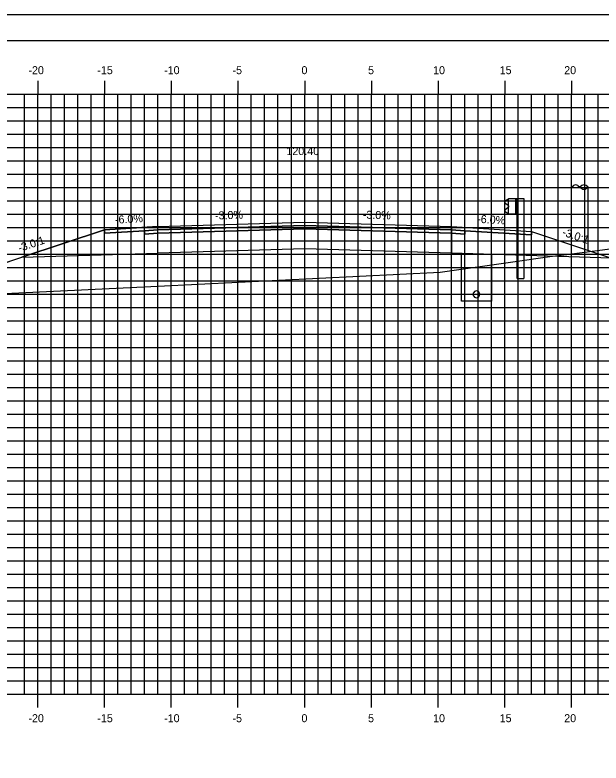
# Model space of a CAD drawing. Extents: x 850598 to 870284, y 366541 to 366651.
# Drawn here: x 852181.5 to 852225.4, y 366595.1 to 366651.2 of the extents above; entities that cross this region are included whole.
import ezdxf

# ---------------------------------------------------------------- set-up
doc = ezdxf.new("R2010")
doc.units = 0
for name, color, linetype in [('ANNOTATION', 7, 'Continuous'), ('BORDER', 7, 'Continuous'), ('D_Drainage_Underdrain', 7, 'Continuous'), ('D_Drainage_Underdrain_06in', 7, 'Continuous'), ('D_Guardrail_Beam_Rt', 7, 'Continuous'), ('D_Roadway_Centerline', 7, 'Continuous'), ('D_Roadway_Centerline_Text', 7, 'Continuous'), ('D_Roadway_Edge_Shoulder', 7, 'Continuous'), ('D_Roadway_Edge_TW', 7, 'Continuous'), ('D_Roadway_Pavement', 7, 'Continuous'), ('D_Roadway_SlopeLines', 7, 'Continuous'), ('D_Roadway_SubGrade', 7, 'Continuous'), ('D_Utilities_Pole_Joint', 7, 'Continuous'), ('H_V ANNOTATION', 7, 'Continuous'), ('MAJOR', 7, 'Continuous'), ('MINOR', 7, 'Continuous'), ('PLOT BOUNDARY', 7, 'Continuous'), ('S_Roadway_Centerline', 7, 'Continuous')]:
    doc.layers.add(name, color=color, linetype=linetype)

msp = doc.modelspace()

# ---------------------------------------------------------------- linework, layer by layer
at = {"layer": 'BORDER'}
msp.add_line((852318.193, 366649.225), (852158.193, 366649.225), dxfattribs=at)
at = {"layer": 'D_Drainage_Underdrain'}
msp.add_lwpolyline([(852217.193, 366633.214), (852217.193, 366629.714), (852214.943, 366629.714), (852214.943, 366633.259)], close=True, dxfattribs=at)
at = {"layer": 'D_Drainage_Underdrain_06in'}
msp.add_lwpolyline([(852216.068, 366630.464), (852215.99, 366630.451), (852215.921, 366630.416), (852215.865, 366630.361), (852215.83, 366630.291), (852215.818, 366630.214), (852215.83, 366630.136), (852215.865, 366630.067), (852215.921, 366630.011), (852215.99, 366629.976), (852216.068, 366629.964), (852216.145, 366629.976), (852216.215, 366630.011), (852216.27, 366630.067), (852216.305, 366630.136), (852216.318, 366630.214), (852216.305, 366630.291), (852216.27, 366630.361), (852216.215, 366630.416), (852216.145, 366630.451)], close=True, dxfattribs=at)
at = {"layer": 'D_Guardrail_Beam_Rt'}
for p, q in [((852218.374, 366637.295), (852218.23, 366637.195)), ((852218.464, 366637.315), (852218.39, 366637.302)), ((852218.464, 366637.39), (852219.151, 366637.39)), ((852218.464, 366636.223), (852218.464, 366637.39)), ((852218.984, 366637.39), (852218.984, 366636.223)), ((852219.089, 366637.39), (852219.089, 366636.223)), ((852219.151, 366637.39), (852219.622, 366637.39)), ((852219.151, 366637.39), (852219.151, 366636.223)), ((852219.622, 366637.39), (852219.622, 366631.39)), ((852218.23, 366637.052), (852218.425, 366636.916)), ((852218.459, 366636.852), (852218.459, 366636.761)), ((852218.425, 366636.696), (852218.23, 366636.56)), ((852218.23, 366636.417), (852218.374, 366636.317)), ((852218.39, 366636.31), (852218.464, 366636.297)), ((852219.151, 366636.223), (852218.464, 366636.223)), ((852219.13, 366631.39), (852219.13, 366636.223)), ((852219.13, 366631.39), (852219.622, 366631.39))]:
    msp.add_line(p, q, dxfattribs=at)
for centre, major_axis, start_param, end_param in [((852218.397, 366637.261), (-0.0417, 0), 4.886922, 5.323254), ((852218.28, 366637.124), (-0.0877, 0), 5.323254, 7.243116), ((852218.38, 366636.852), (0.0789, 0), 0, 0.959931), ((852218.38, 366636.761), (0.0789, 0), 5.323254, 6.283185), ((852218.28, 366636.489), (-0.0877, 0), 5.323254, 7.243116), ((852218.397, 366636.351), (-0.0417, 0), 0.959931, 1.396263)]:
    msp.add_ellipse(centre, major_axis=major_axis, ratio=0.995501, start_param=start_param, end_param=end_param, dxfattribs=at)
at = {"layer": 'D_Roadway_Centerline'}
msp.add_lwpolyline([(852172.715, 366629.897), (852178.193, 366631.723), (852181.995, 366632.99), (852188.193, 366635.056), (852192.193, 366635.296), (852203.193, 366635.626), (852214.193, 366635.296), (852218.193, 366635.056), (852220.193, 366634.936), (852226.193, 366632.936), (852259.379, 366623.225), (852270.022, 366620.111), (852279.884, 366617.225), (852283.884, 366617.225)], dxfattribs=at)
at = {"layer": 'D_Roadway_Edge_Shoulder'}
for points in [[(852192.193, 366635.296), (852188.193, 366635.056), (852188.193, 366634.806), (852191.193, 366634.986), (852192.193, 366635.046)], [(852214.193, 366635.296), (852218.193, 366635.056), (852218.193, 366635.056), (852220.193, 366634.936), (852220.193, 366634.686), (852215.193, 366634.986), (852214.193, 366635.046)]]:
    msp.add_lwpolyline(points, close=True, dxfattribs=at)
at = {"layer": 'D_Roadway_Edge_TW'}
msp.add_lwpolyline([(852192.193, 366635.046), (852192.193, 366635.296), (852203.193, 366635.626), (852214.193, 366635.296), (852214.193, 366635.046), (852203.193, 366635.376)], close=True, dxfattribs=at)
at = {"layer": 'D_Roadway_Pavement'}
for points in [[(852192.193, 366635.046), (852191.193, 366634.986), (852191.193, 366634.736), (852192.193, 366634.796)], [(852192.193, 366634.796), (852192.193, 366635.046), (852203.193, 366635.376), (852214.193, 366635.046), (852214.193, 366634.796), (852203.193, 366635.126)], [(852214.193, 366635.046), (852215.193, 366634.986), (852215.193, 366634.736), (852214.193, 366634.796)]]:
    msp.add_lwpolyline(points, close=True, dxfattribs=at)
at = {"layer": 'D_Roadway_SlopeLines'}
msp.add_lwpolyline([(852192.193, 366635.296), (852188.193, 366635.056), (852178.193, 366631.723)], dxfattribs=at)
at = {"layer": 'D_Roadway_SubGrade'}
for points in [[(852192.193, 366634.796), (852191.193, 366634.736), (852191.193, 366634.986), (852188.193, 366634.806), (852188.193, 366635.056), (852181.995, 366632.99), (852192.193, 366633.296)], [(852192.193, 366633.296), (852192.193, 366634.796), (852203.193, 366635.126), (852214.193, 366634.796), (852214.193, 366633.296), (852203.193, 366633.626)], [(852214.193, 366634.796), (852215.193, 366634.736), (852215.193, 366634.986), (852220.193, 366634.686), (852220.193, 366634.936), (852226.193, 366632.936), (852214.193, 366633.296)]]:
    msp.add_lwpolyline(points, close=True, dxfattribs=at)
at = {"layer": 'D_Utilities_Pole_Joint'}
for p, q in [((852223.193, 366638.256), (852223.349, 366638.366)), ((852223.193, 366633.498), (852223.193, 366638.256)), ((852223.661, 366638.366), (852223.817, 366638.256)), ((852223.974, 366638.366), (852223.817, 366638.256)), ((852223.817, 366638.256), (852223.974, 366638.145)), ((852224.443, 366638.256), (852224.287, 366638.366)), ((852224.287, 366638.145), (852224.443, 366638.256)), ((852224.443, 366633.498), (852224.443, 366638.256))]:
    msp.add_line(p, q, dxfattribs=at)
for centre, start, end in [((852223.505, 366638.145), 90, 125.2644), ((852223.505, 366638.145), 54.7356, 90), ((852224.13, 366638.145), 90, 125.2644), ((852224.13, 366638.145), 54.7356, 90), ((852224.13, 366638.366), 234.7356, 270), ((852224.13, 366638.366), 270, 305.2644)]:
    msp.add_arc(centre, 0.271, start, end, dxfattribs=at)
at = {"layer": 'MAJOR'}
for p, q in [((852183.193, 366646.227), (852183.193, 366645.225)), ((852183.193, 366646.227), (852183.193, 366645.225)), ((852188.193, 366646.227), (852188.193, 366645.225)), ((852188.193, 366646.227), (852188.193, 366645.225)), ((852193.193, 366646.227), (852193.193, 366645.225)), ((852193.193, 366646.227), (852193.193, 366645.225)), ((852198.193, 366646.227), (852198.193, 366645.225)), ((852198.193, 366646.227), (852198.193, 366645.225)), ((852203.193, 366646.227), (852203.193, 366645.225)), ((852203.193, 366646.227), (852203.193, 366645.225)), ((852208.193, 366646.227), (852208.193, 366645.225)), ((852208.193, 366646.227), (852208.193, 366645.225)), ((852213.193, 366646.227), (852213.193, 366645.225)), ((852213.193, 366646.227), (852213.193, 366645.225)), ((852218.193, 366646.227), (852218.193, 366645.225)), ((852218.193, 366646.227), (852218.193, 366645.225)), ((852223.193, 366646.227), (852223.193, 366645.225)), ((852223.193, 366646.227), (852223.193, 366645.225)), ((852163.193, 366645.225), (852303.193, 366645.225)), ((852163.193, 366645.225), (852303.193, 366645.225)), ((852163.193, 366645.225), (852303.193, 366645.225)), ((852163.193, 366645.225), (852303.193, 366645.225)), ((852183.193, 366600.225), (852183.193, 366645.225)), ((852183.193, 366600.225), (852183.193, 366645.225)), ((852188.193, 366600.225), (852188.193, 366645.225)), ((852188.193, 366600.225), (852188.193, 366645.225)), ((852193.193, 366600.225), (852193.193, 366645.225)), ((852193.193, 366600.225), (852193.193, 366645.225)), ((852198.193, 366600.225), (852198.193, 366645.225)), ((852198.193, 366600.225), (852198.193, 366645.225)), ((852203.193, 366600.225), (852203.193, 366645.225)), ((852203.193, 366600.225), (852203.193, 366645.225)), ((852208.193, 366600.225), (852208.193, 366645.225)), ((852208.193, 366600.225), (852208.193, 366645.225)), ((852213.193, 366600.225), (852213.193, 366645.225)), ((852213.193, 366600.225), (852213.193, 366645.225)), ((852218.193, 366600.225), (852218.193, 366645.225)), ((852218.193, 366600.225), (852218.193, 366645.225)), ((852223.193, 366600.225), (852223.193, 366645.225)), ((852223.193, 366600.225), (852223.193, 366645.225)), ((852163.193, 366640.225), (852303.193, 366640.225)), ((852163.193, 366640.225), (852303.193, 366640.225)), ((852163.193, 366635.225), (852303.193, 366635.225)), ((852163.193, 366635.225), (852303.193, 366635.225)), ((852163.193, 366630.225), (852303.193, 366630.225)), ((852163.193, 366630.225), (852303.193, 366630.225)), ((852163.193, 366625.225), (852303.193, 366625.225)), ((852163.193, 366625.225), (852303.193, 366625.225)), ((852163.193, 366620.225), (852303.193, 366620.225)), ((852163.193, 366620.225), (852303.193, 366620.225)), ((852163.193, 366615.225), (852303.193, 366615.225)), ((852163.193, 366615.225), (852303.193, 366615.225)), ((852163.193, 366610.225), (852303.193, 366610.225)), ((852163.193, 366610.225), (852303.193, 366610.225)), ((852163.193, 366605.225), (852303.193, 366605.225)), ((852163.193, 366605.225), (852303.193, 366605.225)), ((852163.193, 366600.225), (852303.193, 366600.225)), ((852163.193, 366600.225), (852303.193, 366600.225)), ((852163.193, 366600.225), (852303.193, 366600.225)), ((852163.193, 366600.225), (852303.193, 366600.225)), ((852183.193, 366599.223), (852183.193, 366600.225)), ((852183.193, 366599.223), (852183.193, 366600.225)), ((852188.193, 366599.223), (852188.193, 366600.225)), ((852188.193, 366599.223), (852188.193, 366600.225)), ((852193.193, 366599.223), (852193.193, 366600.225)), ((852193.193, 366599.223), (852193.193, 366600.225)), ((852198.193, 366599.223), (852198.193, 366600.225)), ((852198.193, 366599.223), (852198.193, 366600.225)), ((852203.193, 366599.223), (852203.193, 366600.225)), ((852203.193, 366599.223), (852203.193, 366600.225)), ((852208.193, 366599.223), (852208.193, 366600.225)), ((852208.193, 366599.223), (852208.193, 366600.225)), ((852213.193, 366599.223), (852213.193, 366600.225)), ((852213.193, 366599.223), (852213.193, 366600.225)), ((852218.193, 366599.223), (852218.193, 366600.225)), ((852218.193, 366599.223), (852218.193, 366600.225)), ((852223.193, 366599.223), (852223.193, 366600.225)), ((852223.193, 366599.223), (852223.193, 366600.225))]:
    msp.add_line(p, q, dxfattribs=at)
at = {"layer": 'MINOR'}
for p, q in [((852182.193, 366600.225), (852182.193, 366645.225)), ((852182.193, 366600.225), (852182.193, 366645.225)), ((852184.193, 366600.225), (852184.193, 366645.225)), ((852184.193, 366600.225), (852184.193, 366645.225)), ((852185.193, 366600.225), (852185.193, 366645.225)), ((852185.193, 366600.225), (852185.193, 366645.225)), ((852186.193, 366600.225), (852186.193, 366645.225)), ((852186.193, 366600.225), (852186.193, 366645.225)), ((852187.193, 366600.225), (852187.193, 366645.225)), ((852187.193, 366600.225), (852187.193, 366645.225)), ((852189.193, 366600.225), (852189.193, 366645.225)), ((852189.193, 366600.225), (852189.193, 366645.225)), ((852190.193, 366600.225), (852190.193, 366645.225)), ((852190.193, 366600.225), (852190.193, 366645.225)), ((852191.193, 366600.225), (852191.193, 366645.225)), ((852191.193, 366600.225), (852191.193, 366645.225)), ((852192.193, 366600.225), (852192.193, 366645.225)), ((852192.193, 366600.225), (852192.193, 366645.225)), ((852194.193, 366600.225), (852194.193, 366645.225)), ((852194.193, 366600.225), (852194.193, 366645.225)), ((852195.193, 366600.225), (852195.193, 366645.225)), ((852195.193, 366600.225), (852195.193, 366645.225)), ((852196.193, 366600.225), (852196.193, 366645.225)), ((852196.193, 366600.225), (852196.193, 366645.225)), ((852197.193, 366600.225), (852197.193, 366645.225)), ((852197.193, 366600.225), (852197.193, 366645.225)), ((852199.193, 366600.225), (852199.193, 366645.225)), ((852199.193, 366600.225), (852199.193, 366645.225)), ((852200.193, 366600.225), (852200.193, 366645.225)), ((852200.193, 366600.225), (852200.193, 366645.225)), ((852201.193, 366600.225), (852201.193, 366645.225)), ((852201.193, 366600.225), (852201.193, 366645.225)), ((852202.193, 366600.225), (852202.193, 366645.225)), ((852202.193, 366600.225), (852202.193, 366645.225)), ((852204.193, 366600.225), (852204.193, 366645.225)), ((852204.193, 366600.225), (852204.193, 366645.225)), ((852205.193, 366600.225), (852205.193, 366645.225)), ((852205.193, 366600.225), (852205.193, 366645.225)), ((852206.193, 366600.225), (852206.193, 366645.225)), ((852206.193, 366600.225), (852206.193, 366645.225)), ((852207.193, 366600.225), (852207.193, 366645.225)), ((852207.193, 366600.225), (852207.193, 366645.225)), ((852209.193, 366600.225), (852209.193, 366645.225)), ((852209.193, 366600.225), (852209.193, 366645.225)), ((852210.193, 366600.225), (852210.193, 366645.225)), ((852210.193, 366600.225), (852210.193, 366645.225)), ((852211.193, 366600.225), (852211.193, 366645.225)), ((852211.193, 366600.225), (852211.193, 366645.225)), ((852212.193, 366600.225), (852212.193, 366645.225)), ((852212.193, 366600.225), (852212.193, 366645.225)), ((852214.193, 366600.225), (852214.193, 366645.225)), ((852214.193, 366600.225), (852214.193, 366645.225)), ((852215.193, 366600.225), (852215.193, 366645.225)), ((852215.193, 366600.225), (852215.193, 366645.225)), ((852216.193, 366600.225), (852216.193, 366645.225)), ((852216.193, 366600.225), (852216.193, 366645.225)), ((852217.193, 366600.225), (852217.193, 366645.225)), ((852217.193, 366600.225), (852217.193, 366645.225)), ((852219.193, 366600.225), (852219.193, 366645.225)), ((852219.193, 366600.225), (852219.193, 366645.225)), ((852220.193, 366600.225), (852220.193, 366645.225)), ((852220.193, 366600.225), (852220.193, 366645.225)), ((852221.193, 366600.225), (852221.193, 366645.225)), ((852221.193, 366600.225), (852221.193, 366645.225)), ((852222.193, 366600.225), (852222.193, 366645.225)), ((852222.193, 366600.225), (852222.193, 366645.225)), ((852224.193, 366600.225), (852224.193, 366645.225)), ((852224.193, 366600.225), (852224.193, 366645.225)), ((852225.193, 366600.225), (852225.193, 366645.225)), ((852225.193, 366600.225), (852225.193, 366645.225)), ((852163.193, 366644.225), (852303.193, 366644.225)), ((852163.193, 366644.225), (852303.193, 366644.225)), ((852163.193, 366643.225), (852303.193, 366643.225)), ((852163.193, 366643.225), (852303.193, 366643.225)), ((852163.193, 366642.225), (852303.193, 366642.225)), ((852163.193, 366642.225), (852303.193, 366642.225)), ((852163.193, 366641.225), (852303.193, 366641.225)), ((852163.193, 366641.225), (852303.193, 366641.225)), ((852163.193, 366639.225), (852303.193, 366639.225)), ((852163.193, 366639.225), (852303.193, 366639.225)), ((852163.193, 366638.225), (852303.193, 366638.225)), ((852163.193, 366638.225), (852303.193, 366638.225)), ((852163.193, 366637.225), (852303.193, 366637.225)), ((852163.193, 366637.225), (852303.193, 366637.225)), ((852163.193, 366636.225), (852303.193, 366636.225)), ((852163.193, 366636.225), (852303.193, 366636.225)), ((852163.193, 366634.225), (852303.193, 366634.225)), ((852163.193, 366634.225), (852303.193, 366634.225)), ((852163.193, 366633.225), (852303.193, 366633.225)), ((852163.193, 366633.225), (852303.193, 366633.225)), ((852163.193, 366632.225), (852303.193, 366632.225)), ((852163.193, 366632.225), (852303.193, 366632.225)), ((852163.193, 366631.225), (852303.193, 366631.225)), ((852163.193, 366631.225), (852303.193, 366631.225)), ((852163.193, 366629.225), (852303.193, 366629.225)), ((852163.193, 366629.225), (852303.193, 366629.225)), ((852163.193, 366628.225), (852303.193, 366628.225)), ((852163.193, 366628.225), (852303.193, 366628.225)), ((852163.193, 366627.225), (852303.193, 366627.225)), ((852163.193, 366627.225), (852303.193, 366627.225)), ((852163.193, 366626.225), (852303.193, 366626.225)), ((852163.193, 366626.225), (852303.193, 366626.225)), ((852163.193, 366624.225), (852303.193, 366624.225)), ((852163.193, 366624.225), (852303.193, 366624.225)), ((852163.193, 366623.225), (852303.193, 366623.225)), ((852163.193, 366623.225), (852303.193, 366623.225)), ((852163.193, 366622.225), (852303.193, 366622.225)), ((852163.193, 366622.225), (852303.193, 366622.225)), ((852163.193, 366621.225), (852303.193, 366621.225)), ((852163.193, 366621.225), (852303.193, 366621.225)), ((852163.193, 366619.225), (852303.193, 366619.225)), ((852163.193, 366619.225), (852303.193, 366619.225)), ((852163.193, 366618.225), (852303.193, 366618.225)), ((852163.193, 366618.225), (852303.193, 366618.225)), ((852163.193, 366617.225), (852303.193, 366617.225)), ((852163.193, 366617.225), (852303.193, 366617.225)), ((852163.193, 366616.225), (852303.193, 366616.225)), ((852163.193, 366616.225), (852303.193, 366616.225)), ((852163.193, 366614.225), (852303.193, 366614.225)), ((852163.193, 366614.225), (852303.193, 366614.225)), ((852163.193, 366613.225), (852303.193, 366613.225)), ((852163.193, 366613.225), (852303.193, 366613.225)), ((852163.193, 366612.225), (852303.193, 366612.225)), ((852163.193, 366612.225), (852303.193, 366612.225)), ((852163.193, 366611.225), (852303.193, 366611.225)), ((852163.193, 366611.225), (852303.193, 366611.225)), ((852163.193, 366609.225), (852303.193, 366609.225)), ((852163.193, 366609.225), (852303.193, 366609.225)), ((852163.193, 366608.225), (852303.193, 366608.225)), ((852163.193, 366608.225), (852303.193, 366608.225)), ((852163.193, 366607.225), (852303.193, 366607.225)), ((852163.193, 366607.225), (852303.193, 366607.225)), ((852163.193, 366606.225), (852303.193, 366606.225)), ((852163.193, 366606.225), (852303.193, 366606.225)), ((852163.193, 366604.225), (852303.193, 366604.225)), ((852163.193, 366604.225), (852303.193, 366604.225)), ((852163.193, 366603.225), (852303.193, 366603.225)), ((852163.193, 366603.225), (852303.193, 366603.225)), ((852163.193, 366602.225), (852303.193, 366602.225)), ((852163.193, 366602.225), (852303.193, 366602.225)), ((852163.193, 366601.225), (852303.193, 366601.225)), ((852163.193, 366601.225), (852303.193, 366601.225))]:
    msp.add_line(p, q, dxfattribs=at)
at = {"layer": 'PLOT BOUNDARY'}
msp.add_lwpolyline([(852150.1, 366541.166), (852320.1, 366541.166), (852320.1, 366651.166), (852150.1, 366651.166)], close=True, dxfattribs=at)
at = {"layer": 'S_Roadway_Centerline'}
msp.add_lwpolyline([(852163.193, 366629.821), (852169.749, 366629.755), (852192.19, 366630.833), (852213.344, 366631.869), (852218.98, 366632.668), (852221.58, 366633.055), (852222.854, 366633.212), (852226.268, 366633.657), (852233.105, 366634.034), (852240.803, 366634.416), (852251.826, 366634.342), (852257.286, 366634.316), (852257.632, 366634.226), (852260.282, 366632.914), (852271.613, 366622.89), (852272.519, 366622.087), (852273.262, 366621.508), (852273.925, 366621.154), (852275.185, 366620.695), (852301.398, 366610.239), (852303.193, 366610.163)], dxfattribs=at)

# ---------------------------------------------------------------- texts
at = {"layer": 'ANNOTATION'}
for s, rotation, p in [('-6.0%', 3.4336, (852188.99, 366635.506)), ('-3.0%', 1.7184, (852196.481, 366635.825)), ('-3.0%', 358.2816, (852207.541, 366635.896)), ('-6.0%', 356.5664, (852216.11, 366635.583)), ('-3.0:1', 341.5651, (852222.447, 366634.639)), ('-3.0:1', 18.4348, (852181.814, 366633.384))]:
    msp.add_text(s, height=0.6, rotation=rotation, dxfattribs=at).set_placement(p)
at = {"layer": 'D_Roadway_Centerline'}
for s, p in [('C', (852203.187, 366635.626)), ('C', (852203.187, 366635.626)), ('L', (852203.193, 366635.619)), ('L', (852203.193, 366635.619))]:
    msp.add_text(s, height=0.0146, dxfattribs=at).set_placement(p)
at = {"layer": 'D_Roadway_Centerline_Text'}
msp.add_text('120.40', height=0.6, dxfattribs=at).set_placement((852201.823, 366640.658))
at = {"layer": 'H_V ANNOTATION'}
for s, p in [('-20', (852182.486, 366646.725)), ('-15', (852187.65, 366646.725)), ('-10', (852192.658, 366646.725)), ('-5', (852197.783, 366646.725)), ('0', (852202.952, 366646.725)), ('5', (852207.944, 366646.725)), ('10', (852212.818, 366646.725)), ('15', (852217.81, 366646.725)), ('20', (852222.647, 366646.725)), ('-20', (852182.486, 366598.125)), ('-15', (852187.65, 366598.125)), ('-10', (852192.658, 366598.125)), ('-5', (852197.783, 366598.125)), ('0', (852202.952, 366598.125)), ('5', (852207.944, 366598.125)), ('10', (852212.818, 366598.125)), ('15', (852217.81, 366598.125)), ('20', (852222.647, 366598.125))]:
    msp.add_text(s, height=0.6, dxfattribs=at).set_placement(p)

doc.saveas('drawing.dxf')
